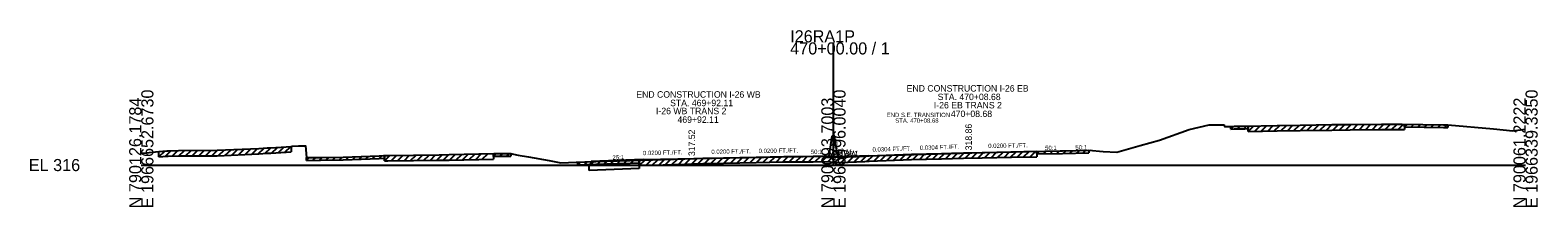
# Model space of a CAD drawing. Extents: x -44 to 4323, y -10 to 9601.
# Drawn here: x 3974.3 to 4322.8, y 7990.3 to 8031.3 of the extents above; entities that cross this region are included whole.
import ezdxf

# ---------------------------------------------------------------- set-up
doc = ezdxf.new("R2010")
doc.units = 0
for name, color, linetype in [('1', 7, 'Continuous'), ('DateStamp', 7, 'Continuous'), ('NotForConst', 7, 'Continuous'), ('QCQA', 7, 'Continuous'), ('RD_SHT_Bndy', 7, 'Continuous'), ('RD_SHT_Iplotshp', 7, 'Continuous'), ('RD_SHT_TX', 7, 'Continuous'), ('RD_XS_ExGround', 7, 'Continuous'), ('RD_XS_MatchLine', 7, 'Continuous'), ('RD_XS_MedBWall', 7, 'Continuous'), ('RD_XS_Misc_Line', 7, 'Continuous'), ('RD_XS_PaveShd', 7, 'Continuous'), ('RD_XS_TX_Elev_PR', 7, 'Continuous'), ('RD_XS_TX_Profile', 7, 'Continuous'), ('RD_XS_TX_ShdSlope', 7, 'Continuous'), ('RD_XS_TX_Slope', 7, 'Continuous'), ('seal', 7, 'Continuous'), ('TR SN EXTRUDED PANEL SIGNS - GROUND MOUNTED', 7, 'Continuous')]:
    doc.layers.add(name, color=color, linetype=linetype)

msp = doc.modelspace()

# ---------------------------------------------------------------- linework, layer by layer
at = {"layer": 'DateStamp'}
msp.add_lwpolyline([(4000, 8002.75), (4000.38, 8002.78), (4004.09, 8003.15), (4005.9, 8003.31), (4006.23, 8003.32), (4008.63, 8003.35), (4017.53, 8003.42), (4027.15, 8003.85), (4029.09, 8003.98), (4029.91, 8004), (4034.67, 8004.29), (4034.88, 8004.41), (4036.31, 8004.42), (4037.94, 8004.44), (4038.16, 8001.71), (4041.43, 8001.78), (4046.63, 8001.86), (4054.96, 8002.16), (4055.98, 8002.21), (4056.96, 8002.22), (4068.88, 8002.35), (4071.15, 8002.41), (4081.49, 8002.64), (4083.76, 8002.69), (4085.4, 8002.71), (4086.06, 8002.55), (4087.15, 8002.27), (4089.48, 8001.88), (4094.3, 8001.05), (4097.01, 8000.52), (4100.51, 8000.63), (4100.89, 8000.65), (4102.55, 8000.72), (4110.05, 8001.01), (4113, 8001.07), (4118.16, 8001.2), (4125.63, 8001.44), (4129.78, 8001.58), (4134.55, 8001.68), (4142.12, 8001.85), (4148.55, 8001.96), (4153.02, 8002.01), (4155.32, 8002.03), (4158.71, 8002.06), (4160.05, 8001.94), (4161.47, 8001.81), (4167.27, 8002.09), (4167.66, 8002.11), (4168.25, 8002.14), (4178.03, 8002.52), (4184.97, 8002.69), (4190.05, 8002.82), (4194.39, 8002.91), (4201.13, 8003.06), (4212.96, 8003.31), (4219.02, 8003.44), (4222.34, 8003.16), (4225.48, 8002.97), (4230.9, 8004.53), (4235.4, 8005.8), (4242.22, 8008.21), (4246.83, 8009.29), (4249.44, 8009.32), (4250.3, 8009.34), (4250.4, 8008.89), (4251.88, 8008.95), (4252.61, 8008.97), (4255.14, 8009.04), (4262.59, 8009.16), (4267.9, 8009.25), (4275.22, 8009.36), (4279.48, 8009.42), (4286.66, 8009.45), (4291.44, 8009.47), (4301.02, 8009.33), (4302.06, 8009.32), (4312.57, 8008.38), (4317.04, 8007.93), (4320, 8008.34)], dxfattribs=at)
at = {"layer": 'NotForConst'}
for p, q in [((4269.45, 8008.02), (4270.72, 8009.29)), ((4270.95, 8008.04), (4272.23, 8009.31)), ((4272.46, 8008.07), (4273.74, 8009.34)), ((4273.97, 8008.09), (4275.24, 8009.36)), ((4275.47, 8008.11), (4276.75, 8009.38)), ((4276.98, 8008.14), (4278.25, 8009.41)), ((4278.48, 8008.16), (4279.76, 8009.43)), ((4279.99, 8008.18), (4281.25, 8009.43)), ((4281.5, 8008.18), (4282.76, 8009.44)), ((4283, 8008.19), (4284.26, 8009.44)), ((4284.51, 8008.19), (4285.77, 8009.45)), ((4286.01, 8008.2), (4287.27, 8009.45)), ((4287.52, 8008.2), (4288.78, 8009.46)), ((4289.03, 8008.21), (4290.29, 8009.47)), ((4290.53, 8008.22), (4291.79, 8009.46)), ((4292.05, 8008.84), (4292.68, 8009.45)), ((4293.58, 8008.81), (4294.21, 8009.43)), ((4295.11, 8008.79), (4295.74, 8009.41)), ((4296.64, 8008.77), (4297.27, 8009.39)), ((4298.17, 8008.75), (4298.8, 8009.36)), ((4299.7, 8008.73), (4300.33, 8009.34)), ((4301.23, 8008.7), (4301.86, 8009.32)), ((4251.88, 8008.33), (4252.53, 8008.97)), ((4253.41, 8008.37), (4254.06, 8009.01)), ((4254.94, 8008.41), (4255.59, 8009.05)), ((4255.9, 8007.8), (4257.17, 8009.07)), ((4257.4, 8007.83), (4258.68, 8009.1)), ((4258.91, 8007.85), (4260.18, 8009.12)), ((4260.41, 8007.87), (4261.69, 8009.14)), ((4261.92, 8007.9), (4263.19, 8009.17)), ((4263.43, 8007.92), (4264.7, 8009.19)), ((4264.93, 8007.95), (4266.21, 8009.22)), ((4266.44, 8007.97), (4267.71, 8009.24)), ((4267.94, 8008), (4269.22, 8009.27)), ((4004.09, 8001.9), (4005.5, 8003.28)), ((4005.62, 8002.04), (4006.94, 8003.33)), ((4007.15, 8002.08), (4008.45, 8003.35)), ((4008.69, 8002.1), (4009.97, 8003.36)), ((4010.22, 8002.11), (4011.5, 8003.37)), ((4011.75, 8002.12), (4013.03, 8003.38)), ((4013.28, 8002.13), (4014.56, 8003.39)), ((4014.81, 8002.14), (4016.09, 8003.4)), ((4016.34, 8002.16), (4017.63, 8003.42)), ((4017.87, 8002.18), (4019.21, 8003.49)), ((4019.4, 8002.25), (4020.74, 8003.56)), ((4020.93, 8002.32), (4022.27, 8003.63)), ((4022.46, 8002.39), (4023.8, 8003.7)), ((4023.99, 8002.46), (4025.33, 8003.77)), ((4025.52, 8002.53), (4026.86, 8003.84)), ((4027.05, 8002.6), (4028.42, 8003.94)), ((4028.58, 8002.7), (4029.92, 8004)), ((4030.11, 8002.77), (4031.47, 8004.1)), ((4031.64, 8002.86), (4033, 8004.19)), ((4033.17, 8002.95), (4034.53, 8004.28)), ((4065.26, 8001.06), (4066.53, 8002.32)), ((4066.76, 8001.07), (4068.03, 8002.34)), ((4068.27, 8001.09), (4069.55, 8002.36)), ((4069.78, 8001.12), (4071.07, 8002.41)), ((4071.28, 8001.16), (4072.57, 8002.44)), ((4072.79, 8001.2), (4074.07, 8002.47)), ((4074.29, 8001.23), (4075.58, 8002.51)), ((4075.8, 8001.26), (4077.08, 8002.54)), ((4077.31, 8001.3), (4078.59, 8002.58)), ((4078.81, 8001.33), (4080.1, 8002.61)), ((4081.39, 8002.01), (4082.04, 8002.65)), ((4082.92, 8002.05), (4083.57, 8002.69)), ((4084.45, 8002.07), (4085.1, 8002.71)), ((4172.35, 8001.05), (4173.65, 8002.35)), ((4173.85, 8001.1), (4175.16, 8002.41)), ((4175.36, 8001.16), (4176.66, 8002.46)), ((4176.86, 8001.22), (4178.17, 8002.52)), ((4178.37, 8001.28), (4179.66, 8002.56)), ((4179.88, 8001.31), (4181.16, 8002.6)), ((4181.38, 8001.35), (4182.67, 8002.63)), ((4182.89, 8001.39), (4184.18, 8002.67)), ((4184.39, 8001.43), (4185.68, 8002.71)), ((4185.9, 8001.46), (4187.19, 8002.75)), ((4187.41, 8001.5), (4188.69, 8002.78)), ((4188.91, 8001.54), (4190.2, 8002.82)), ((4190.42, 8001.57), (4191.7, 8002.85)), ((4191.92, 8001.61), (4193.21, 8002.88)), ((4193.43, 8001.64), (4194.71, 8002.92)), ((4194.94, 8001.67), (4196.22, 8002.95)), ((4196.44, 8001.7), (4197.73, 8002.98)), ((4197.95, 8001.74), (4199.23, 8003.02)), ((4199.45, 8001.77), (4200.74, 8003.05)), ((4200.96, 8001.81), (4202.24, 8003.08)), ((4202.47, 8001.84), (4203.75, 8003.12)), ((4203.97, 8001.87), (4205.25, 8003.15)), ((4205.48, 8001.9), (4206.76, 8003.18)), ((4207.02, 8002.56), (4207.67, 8003.2)), ((4208.55, 8002.59), (4209.2, 8003.23)), ((4210.08, 8002.63), (4210.73, 8003.26)), ((4211.61, 8002.66), (4212.26, 8003.3)), ((4213.14, 8002.69), (4213.79, 8003.33)), ((4214.67, 8002.72), (4215.32, 8003.36)), ((4216.2, 8002.76), (4216.85, 8003.4)), ((4217.73, 8002.79), (4218.38, 8003.43)), ((4038.16, 8001.09), (4038.81, 8001.73)), ((4039.69, 8001.12), (4040.34, 8001.76)), ((4041.22, 8001.15), (4041.87, 8001.79)), ((4042.75, 8001.18), (4043.4, 8001.81)), ((4044.28, 8001.2), (4044.93, 8001.84)), ((4045.81, 8001.22), (4046.46, 8001.86)), ((4047.34, 8001.26), (4048, 8001.91)), ((4048.87, 8001.32), (4049.53, 8001.97)), ((4050.4, 8001.37), (4051.06, 8002.02)), ((4051.93, 8001.43), (4052.59, 8002.08)), ((4053.46, 8001.48), (4054.12, 8002.13)), ((4054.99, 8001.54), (4055.66, 8002.19)), ((4056.22, 8000.96), (4057.49, 8002.23)), ((4057.73, 8000.98), (4059, 8002.24)), ((4059.23, 8000.99), (4060.5, 8002.26)), ((4060.74, 8001.01), (4062.01, 8002.27)), ((4062.25, 8001.03), (4063.51, 8002.29)), ((4063.75, 8001.04), (4065.02, 8002.31)), ((4100.89, 8000.03), (4101.56, 8000.68)), ((4102.42, 8000.09), (4103.09, 8000.74)), ((4103.95, 8000.15), (4104.62, 8000.8)), ((4105.48, 8000.2), (4106.15, 8000.86)), ((4107.01, 8000.26), (4107.68, 8000.91)), ((4108.54, 8000.32), (4109.2, 8000.97)), ((4110.07, 8000.38), (4110.72, 8001.02)), ((4111.6, 8000.42), (4112.25, 8001.06)), ((4113.13, 8000.45), (4113.78, 8001.09)), ((4115.12, 7999.88), (4116.41, 8001.16)), ((4116.63, 7999.91), (4117.91, 8001.19)), ((4118.13, 7999.95), (4119.43, 8001.24)), ((4119.64, 8000), (4120.93, 8001.29)), ((4121.14, 8000.04), (4122.44, 8001.34)), ((4122.65, 8000.09), (4123.95, 8001.38)), ((4124.16, 8000.14), (4125.45, 8001.43)), ((4125.66, 8000.19), (4126.96, 8001.48)), ((4127.17, 8000.24), (4128.47, 8001.54)), ((4128.67, 8000.3), (4129.97, 8001.59)), ((4130.18, 8000.34), (4131.46, 8001.62)), ((4131.69, 8000.37), (4132.97, 8001.65)), ((4133.19, 8000.41), (4134.47, 8001.68)), ((4134.7, 8000.44), (4135.98, 8001.72)), ((4136.2, 8000.47), (4137.49, 8001.75)), ((4137.71, 8000.51), (4138.99, 8001.78)), ((4139.22, 8000.54), (4140.5, 8001.82)), ((4140.72, 8000.57), (4142, 8001.85)), ((4142.23, 8000.61), (4143.5, 8001.88)), ((4143.73, 8000.63), (4145.01, 8001.9)), ((4145.24, 8000.65), (4146.51, 8001.92)), ((4146.74, 8000.68), (4148.02, 8001.95)), ((4148.25, 8000.7), (4149.52, 8001.97)), ((4149.76, 8000.72), (4151.03, 8001.99)), ((4151.26, 8000.74), (4152.53, 8002.01)), ((4152.77, 8000.76), (4154.04, 8002.02)), ((4154.27, 8000.77), (4155.54, 8002.03)), ((4155.78, 8000.79), (4157.05, 8002.05)), ((4157.29, 8000.8), (4158.55, 8002.06)), ((4158.79, 8000.8), (4159.94, 8001.95)), ((4160.3, 8000.66), (4161.45, 8001.81)), ((4161.8, 8000.57), (4163.13, 8001.89)), ((4163.31, 8000.65), (4164.63, 8001.96)), ((4164.82, 8000.72), (4166.14, 8002.04)), ((4166.32, 8000.8), (4167.64, 8002.11)), ((4167.83, 8000.87), (4169.13, 8002.17)), ((4169.33, 8000.93), (4170.64, 8002.23)), ((4170.84, 8000.99), (4172.15, 8002.29))]:
    msp.add_line(p, q, dxfattribs=at)
at = {"layer": 'QCQA'}
for p, q in [((4168.25, 8002.14), (4178.03, 8002.52)), ((4178.03, 8002.52), (4184.97, 8002.69)), ((4184.97, 8002.69), (4190.05, 8002.82)), ((4187.32, 8002.76), (4216, 8003.38)), ((4190.05, 8002.82), (4194.39, 8002.91)), ((4194.39, 8002.91), (4201.13, 8003.06)), ((4201.13, 8003.06), (4207.02, 8003.19)), ((4115.12, 8001.13), (4118.16, 8001.2)), ((4115.12, 8001.13), (4115.12, 7999.21)), ((4118.16, 8001.2), (4125.63, 8001.44)), ((4125.63, 8001.44), (4129.78, 8001.58)), ((4129.78, 8001.58), (4134.55, 8001.68)), ((4134.55, 8001.68), (4142.12, 8001.85)), ((4142.12, 8001.85), (4148.55, 8001.96)), ((4148.55, 8001.96), (4153.02, 8002.01)), ((4153.02, 8002.01), (4155.32, 8002.03)), ((4155.32, 8002.03), (4158.71, 8002.06)), ((4158.71, 8002.06), (4160.05, 8001.94)), ((4160.05, 8001.94), (4161.47, 8001.81)), ((4161.47, 8001.81), (4167.27, 8002.09)), ((4167.27, 8002.09), (4167.66, 8002.11)), ((4167.66, 8002.11), (4168.25, 8002.14))]:
    msp.add_line(p, q, dxfattribs=at)
at = {"layer": 'RD_SHT_Bndy'}
for p, q in [((4160, 8000), (4160, 8028.41)), ((4000, 8000), (4160, 8000)), ((4160, 8000), (4320, 8000))]:
    msp.add_line(p, q, dxfattribs=at)
at = {"layer": 'RD_SHT_Iplotshp'}
for p, q in [((4292.05, 8009.46), (4292.05, 8008.21)), ((4292.05, 8008.84), (4292.05, 8009.46)), ((4302.06, 8009.32), (4302.06, 8008.69)), ((4251.88, 8008.33), (4251.88, 8008.95)), ((4251.88, 8008.33), (4252.61, 8008.35)), ((4252.61, 8008.35), (4255.14, 8008.42)), ((4255.14, 8008.42), (4255.9, 8008.43)), ((4255.9, 8007.8), (4255.9, 8009.05)), ((4255.9, 8009.05), (4255.9, 8008.43)), ((4255.9, 8007.8), (4262.59, 8007.91)), ((4262.59, 8007.91), (4267.9, 8008)), ((4267.9, 8008), (4275.22, 8008.11)), ((4275.22, 8008.11), (4279.48, 8008.17)), ((4279.48, 8008.17), (4286.66, 8008.2)), ((4286.66, 8008.2), (4291.44, 8008.22)), ((4291.44, 8008.22), (4292.05, 8008.21)), ((4292.05, 8008.84), (4301.02, 8008.71)), ((4301.02, 8008.71), (4302.06, 8008.69)), ((4004.09, 8001.9), (4004.09, 8003.15)), ((4017.53, 8002.17), (4027.15, 8002.6)), ((4027.15, 8002.6), (4029.09, 8002.73)), ((4029.09, 8002.73), (4029.91, 8002.75)), ((4029.91, 8002.75), (4034.67, 8003.04)), ((4034.67, 8004.29), (4034.67, 8003.04)), ((4081.39, 8002.64), (4081.39, 8001.39)), ((4081.39, 8002.01), (4081.39, 8002.64)), ((4085.4, 8002.71), (4085.4, 8002.09)), ((4207.02, 8003.19), (4207.02, 8001.94)), ((4207.02, 8002.56), (4207.02, 8003.19)), ((4207.02, 8002.56), (4212.96, 8002.69)), ((4212.96, 8002.69), (4219.02, 8002.82)), ((4219.02, 8003.44), (4219.02, 8002.82)), ((4004.09, 8001.9), (4005.9, 8002.06)), ((4005.9, 8002.06), (4006.23, 8002.07)), ((4006.23, 8002.07), (4008.63, 8002.1)), ((4008.63, 8002.1), (4017.53, 8002.17)), ((4038.16, 8001.09), (4038.16, 8001.71)), ((4038.16, 8001.09), (4041.43, 8001.15)), ((4041.43, 8001.15), (4046.63, 8001.24)), ((4046.63, 8001.24), (4054.96, 8001.53)), ((4054.96, 8001.53), (4055.98, 8001.58)), ((4055.98, 8001.58), (4056.22, 8001.58)), ((4056.22, 8000.96), (4056.22, 8002.21)), ((4056.22, 8002.21), (4056.22, 8001.58)), ((4056.22, 8000.96), (4056.96, 8000.97)), ((4056.96, 8000.97), (4068.88, 8001.1)), ((4068.88, 8001.1), (4071.15, 8001.16)), ((4071.15, 8001.16), (4081.39, 8001.39)), ((4081.39, 8002.01), (4081.49, 8002.02)), ((4081.49, 8002.02), (4083.76, 8002.07)), ((4083.76, 8002.07), (4085.4, 8002.09)), ((4100.89, 8000.03), (4100.89, 8000.65)), ((4100.89, 8000.03), (4102.55, 8000.09)), ((4102.55, 8000.09), (4110.05, 8000.38)), ((4110.05, 8000.38), (4113, 8000.45)), ((4113, 8000.45), (4115.12, 8000.5)), ((4115.12, 7999.88), (4115.12, 8001.13)), ((4115.12, 8001.13), (4115.12, 8000.5)), ((4115.12, 7999.88), (4118.16, 7999.95)), ((4118.16, 7999.95), (4125.63, 8000.19)), ((4125.63, 8000.19), (4129.78, 8000.33)), ((4129.78, 8000.33), (4134.55, 8000.43)), ((4134.55, 8000.43), (4142.12, 8000.6)), ((4142.12, 8000.6), (4148.55, 8000.71)), ((4148.55, 8000.71), (4153.02, 8000.76)), ((4153.02, 8000.76), (4155.32, 8000.78)), ((4155.32, 8000.78), (4158.71, 8000.81)), ((4158.71, 8000.81), (4160.05, 8000.69)), ((4160.05, 8000.69), (4161.47, 8000.56)), ((4161.47, 8000.56), (4167.27, 8000.84)), ((4167.27, 8000.84), (4167.66, 8000.86)), ((4167.66, 8000.86), (4168.25, 8000.89)), ((4168.25, 8000.89), (4178.03, 8001.27)), ((4178.03, 8001.27), (4184.97, 8001.44)), ((4184.97, 8001.44), (4190.05, 8001.57)), ((4190.05, 8001.57), (4194.39, 8001.66)), ((4194.39, 8001.66), (4201.13, 8001.81)), ((4201.13, 8001.81), (4207.02, 8001.94))]:
    msp.add_line(p, q, dxfattribs=at)
at = {"layer": 'RD_XS_Misc_Line'}
for p, q in [((4103.5, 8000.22), (4104, 8000.24)), ((4103.5, 7998.74), (4103.5, 8000.22)), ((4115.12, 7999.21), (4103.5, 7998.74)), ((4104, 8000.24), (4104, 8000.8))]:
    msp.add_line(p, q, dxfattribs=at)
at = {"layer": 'RD_XS_PaveShd'}
msp.add_line((4216, 8003.34), (4219.46, 8003.41), dxfattribs=at)
at = {"layer": 'RD_XS_TX_Elev_PR'}
for p, q in [((4187.32, 8002.76), (4216, 8003.34)), ((4116, 8001.28), (4104, 8000.8)), ((4152, 8002), (4160, 8002.16)), ((4160, 8002.16), (4160, 8001.81)), ((4168, 8002.13), (4160, 8001.81)), ((4160, 8001.81), (4160, 8001.93))]:
    msp.add_line(p, q, dxfattribs=at)
at = {"layer": 'RD_XS_TX_ShdSlope'}
for p, q in [((4159, 8002.14), (4159.67, 8006.65)), ((4160.33, 8006.65), (4159.67, 8006.65)), ((4160.33, 8006.31), (4160.33, 8006.65)), ((4161, 8001.84), (4160.33, 8006.31))]:
    msp.add_line(p, q, dxfattribs=at)
at = {"layer": 'RD_XS_TX_Slope'}
for p, q in [((4168, 8002.13), (4192, 8002.86)), ((4192, 8002.86), (4204, 8003.1)), ((4116, 8001.28), (4128, 8001.52)), ((4128, 8001.52), (4152, 8002))]:
    msp.add_line(p, q, dxfattribs=at)

# ---------------------------------------------------------------- texts
at = {"layer": '1'}
for s, p in [('I-26 WB TRANS 2', (4118.99, 8011.77)), ('I-26 EB TRANS 2', (4183.22, 8013.11)), ('469+92.11', (4123.95, 8009.77)), ('470+08.68', (4187.14, 8011.11))]:
    msp.add_text(s, height=1.5, dxfattribs=at).set_placement(p)
at = {"layer": 'RD_SHT_Bndy'}
for s, p in [('I26RA1P', (4150, 8028.41)), ('470+00.00 / 1', (4150, 8025.61)), ('EL 316', (3974, 7998.6))]:
    msp.add_text(s, height=2.8, dxfattribs=at).set_placement(p)
for s, p in [('E 1966652.6730', (4002.8, 7990)), ('E 1966496.0040', (4162.8, 7990)), ('E 1966339.3350', (4322.8, 7990)), ('N 790126.1784', (4000, 7990)), ('N 790093.7003', (4160, 7990)), ('N 790061.2222', (4320, 7990))]:
    msp.add_text(s, height=2.8, rotation=90, dxfattribs=at).set_placement(p)
at = {"layer": 'RD_SHT_TX'}
msp.add_text('317.94', height=1, rotation=90, dxfattribs=at).set_placement((4161, 8001.94))
at = {"layer": 'RD_XS_ExGround'}
for s, rotation, p in [('25:1', 2.2906, (4108.94, 8001.25)), ('50:1', 1.4175, (4154.78, 8002.54)), ('25:1', 2.2906, (4162.94, 8002.18)), ('50:1', 1.1458, (4208.94, 8003.45))]:
    msp.add_text(s, height=1, rotation=rotation, dxfattribs=at).set_placement(p)
at = {"layer": 'RD_XS_MatchLine'}
for s, height, p in [('END CONSTRUCTION I-26 WB', 1.5, (4114.43, 8015.6)), ('END CONSTRUCTION I-26 EB', 1.5, (4176.92, 8017.01)), ('STA. 470+08.68', 1.5, (4184.1, 8015.04)), ('STA. 469+92.11', 1.5, (4122.25, 8013.63)), ('END S.E. TRANSITION', 1, (4172.32, 8011.11)), ('STA. 470+08.68', 1, (4174.29, 8009.8))]:
    msp.add_text(s, height=height, dxfattribs=at).set_placement(p)
at = {"layer": 'RD_XS_MedBWall'}
msp.add_text('50:1', height=1, rotation=1.1458, dxfattribs=at).set_placement((4215.94, 8003.59))
at = {"layer": 'RD_XS_TX_Profile'}
for s, p in [('WBW', (4159, 8002.14)), ('EBW', (4161, 8001.84))]:
    msp.add_text(s, height=1.5, dxfattribs=at).set_placement(p)
at = {"layer": 'seal'}
for s, p in [(' 318.86', (4192, 8002.86)), (' 317.52', (4128, 8001.52))]:
    msp.add_text(s, height=1.5, rotation=90, dxfattribs=at).set_placement(p)
at = {"layer": 'TR SN EXTRUDED PANEL SIGNS - GROUND MOUNTED'}
for s, rotation, p in [('0.0200 FT./FT.', 1.1458, (4115.98, 8002.28)), ('0.0200 FT./FT.', 0.7276, (4131.79, 8002.57)), ('0.0200 FT./FT.', 0.7276, (4142.71, 8002.77)), ('0.0304 FT./FT.', 1.7413, (4169.05, 8003.08)), ('0.0304 FT./FT.', 1.7413, (4179.97, 8003.49)), ('0.0200 FT./FT.', 1.1458, (4195.79, 8003.93))]:
    msp.add_text(s, height=1, rotation=rotation, dxfattribs=at).set_placement(p)

doc.saveas('drawing.dxf')
